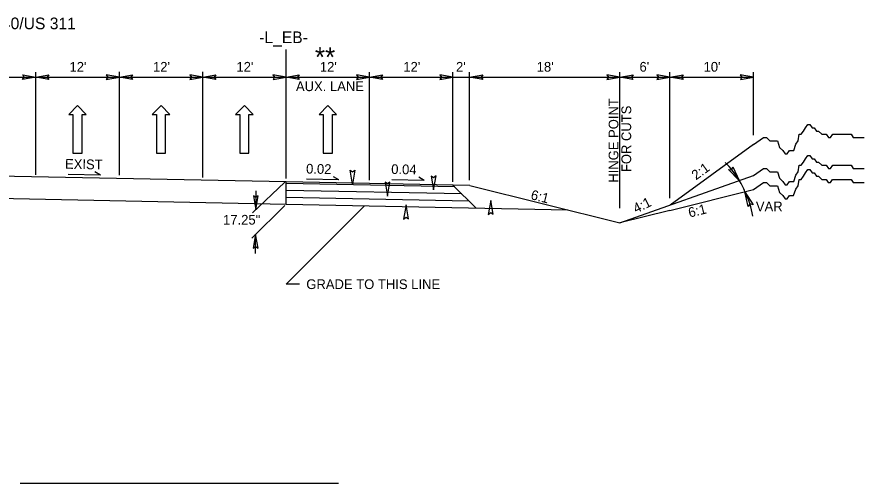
# Model space of a CAD drawing. Extents: x 1725232 to 1728895, y 538685 to 540544.
# Drawn here: x 1727602 to 1728211, y 540208 to 540544 of the extents above; entities that cross this region are included whole.
import ezdxf

# ---------------------------------------------------------------- set-up
doc = ezdxf.new("R2010")
doc.units = 0
for name, color, linetype in [('Default', 7, 'Continuous'), ('Prop Dimension Text', 7, 'Continuous'), ('Typical Hinge Slope Interstate CELL', 7, 'Continuous'), ('Typical Pavement Slope CELL', 7, 'Continuous'), ('Typical Pavement Slope Information CELL', 7, 'Continuous'), ('Typical Terminator CELL', 7, 'Continuous'), ('Typical Text Centerline CELL', 7, 'Continuous'), ('Typical Text General CELL', 7, 'Continuous')]:
    doc.layers.add(name, color=color, linetype=linetype)

msp = doc.modelspace()

# ---------------------------------------------------------------- linework, layer by layer
at = {"layer": 'Default'}
for p, q in [((1727795.33, 540427.18), (1727795.33, 540520.09)), ((1727615.18, 540429.8), (1727615.18, 540503.77)), ((1727675.34, 540429.58), (1727675.34, 540503.92)), ((1727735.39, 540427.79), (1727735.39, 540503.89)), ((1727795.33, 540427.18), (1727795.33, 540503.89)), ((1727855.37, 540425.98), (1727855.37, 540503.77)), ((1727915.42, 540425.98), (1727915.42, 540503.77)), ((1727915.42, 540424.78), (1727915.42, 540503.77)), ((1727927.43, 540425.98), (1727927.43, 540503.77)), ((1728035.55, 540405.77), (1728035.55, 540503.77)), ((1728071.58, 540412.81), (1728071.58, 540503.77)), ((1728131.63, 540458.2), (1728131.63, 540503.77)), ((1727561.09, 540500.07), (1727615.29, 540500.07)), ((1727615.29, 540500.07), (1727675.34, 540500.07)), ((1727675.34, 540500.07), (1727735.39, 540500.07)), ((1727735.39, 540500.07), (1727795.43, 540500.07)), ((1727795.43, 540500.07), (1727855.48, 540500.07)), ((1727855.48, 540500.07), (1727915.53, 540500.07)), ((1727855.48, 540500.07), (1727915.53, 540500.07)), ((1727915.53, 540500.07), (1727927.43, 540500.07)), ((1727927.43, 540500.07), (1728035.51, 540500.07)), ((1728035.51, 540500.07), (1728071.54, 540500.07)), ((1728071.54, 540500.07), (1728131.59, 540500.07)), ((1727645.32, 540479.59), (1727638.92, 540473.29)), ((1727651.52, 540473.29), (1727645.32, 540479.59)), ((1727705.36, 540479.59), (1727698.96, 540473.29)), ((1727711.56, 540473.29), (1727705.36, 540479.59)), ((1727765.41, 540479.59), (1727759.01, 540473.29)), ((1727771.61, 540473.29), (1727765.41, 540479.59)), ((1727825.46, 540479.59), (1727819.06, 540473.29)), ((1727831.66, 540473.29), (1727825.46, 540479.59)), ((1727638.92, 540473.29), (1727641.92, 540473.29)), ((1727641.92, 540473.29), (1727641.92, 540445.29)), ((1727648.52, 540445.29), (1727648.52, 540473.29)), ((1727648.52, 540473.29), (1727651.52, 540473.29)), ((1727698.96, 540473.29), (1727701.96, 540473.29)), ((1727701.96, 540473.29), (1727701.96, 540445.29)), ((1727708.56, 540445.29), (1727708.56, 540473.29)), ((1727708.56, 540473.29), (1727711.56, 540473.29)), ((1727759.01, 540473.29), (1727762.01, 540473.29)), ((1727762.01, 540473.29), (1727762.01, 540445.29)), ((1727768.61, 540445.29), (1727768.61, 540473.29)), ((1727768.61, 540473.29), (1727771.61, 540473.29)), ((1727819.06, 540473.29), (1727822.06, 540473.29)), ((1727822.06, 540473.29), (1727822.06, 540445.29)), ((1727828.66, 540445.29), (1727828.66, 540473.29)), ((1727828.66, 540473.29), (1727831.66, 540473.29)), ((1727641.92, 540445.29), (1727648.52, 540445.29)), ((1727701.96, 540445.29), (1727708.56, 540445.29)), ((1727762.01, 540445.29), (1727768.61, 540445.29)), ((1727822.06, 540445.29), (1727828.66, 540445.29)), ((1727794.5, 540424.56), (1727771.21, 540402.26)), ((1727773.55, 540418.26), (1727773.55, 540404.5)), ((1727794.5, 540407.67), (1727770.67, 540384.19)), ((1727773.43, 540373.15), (1727773.43, 540386.91)), ((1727603.93, 540207.63), (1727833.1, 540207.63))]:
    msp.add_line(p, q, dxfattribs=at)
for points in [[(1727605.81, 540501.69), (1727615.18, 540500.07), (1727605.75, 540498.4), (1727606.95, 540500.07)], [(1727624.56, 540498.45), (1727615.18, 540500.07), (1727624.61, 540501.74), (1727623.42, 540500.07)], [(1727665.96, 540498.45), (1727675.34, 540500.07), (1727665.91, 540501.74), (1727667.11, 540500.07)], [(1727684.72, 540498.45), (1727675.34, 540500.07), (1727684.77, 540501.74), (1727683.57, 540500.07)], [(1727726.01, 540498.45), (1727735.39, 540500.07), (1727725.96, 540501.74), (1727727.16, 540500.07)], [(1727744.77, 540498.45), (1727735.39, 540500.07), (1727744.82, 540501.74), (1727743.62, 540500.07)], [(1727785.95, 540498.45), (1727795.33, 540500.07), (1727785.9, 540501.74), (1727787.09, 540500.07)], [(1727804.7, 540498.45), (1727795.33, 540500.07), (1727804.76, 540501.74), (1727803.56, 540500.07)], [(1727845.99, 540498.45), (1727855.37, 540500.07), (1727845.94, 540501.74), (1727847.14, 540500.07)], [(1727864.75, 540498.45), (1727855.37, 540500.07), (1727864.8, 540501.74), (1727863.6, 540500.07)], [(1727906.04, 540498.45), (1727915.42, 540500.07), (1727905.99, 540501.74), (1727907.19, 540500.07)], [(1727936.81, 540498.45), (1727927.43, 540500.07), (1727936.86, 540501.74), (1727935.66, 540500.07)], [(1728026.17, 540498.46), (1728035.55, 540500.08), (1728026.12, 540501.74), (1728027.32, 540500.08)], [(1728044.93, 540498.46), (1728035.55, 540500.08), (1728044.98, 540501.74), (1728043.78, 540500.08)], [(1728062.2, 540498.46), (1728071.58, 540500.08), (1728062.15, 540501.74), (1728063.35, 540500.08)], [(1728080.96, 540498.46), (1728071.58, 540500.08), (1728081.01, 540501.74), (1728079.81, 540500.08)], [(1728122.21, 540498.45), (1728131.59, 540500.07), (1728122.16, 540501.74), (1728123.36, 540500.07)], [(1728116.91, 540435.57), (1728121.46, 540425.59), (1728113.75, 540433.49), (1728116.12, 540433.43)], [(1728127.83, 540406.84), (1728125.5, 540417.56), (1728131.36, 540408.2), (1728129.06, 540408.76)], [(1728127.83, 540406.84), (1728125.5, 540417.56), (1728131.36, 540408.2), (1728129.06, 540408.76)]]:
    msp.add_lwpolyline(points, close=True, dxfattribs=at)
at = {"layer": 'Typical Hinge Slope Interstate CELL'}
for points in [[(1728131.59, 540451.51), (1728138.81, 540456.57), (1728141.15, 540456.57), (1728143.48, 540454.24), (1728145.04, 540454.24), (1728147.38, 540454.24), (1728148.93, 540454.24), (1728150.49, 540449.55), (1728152.83, 540447.23), (1728154.39, 540444.88), (1728155.94, 540444.88), (1728157.5, 540447.23), (1728159.06, 540447.23), (1728160.61, 540447.23), (1728162.17, 540451.9), (1728163.73, 540454.24), (1728164.51, 540458.92), (1728166.07, 540458.92), (1728167.63, 540461.24), (1728169.18, 540463.59), (1728170.74, 540465.93), (1728172.3, 540465.93), (1728173.85, 540463.59), (1728175.41, 540463.59), (1728176.97, 540461.24), (1728178.53, 540461.24), (1728180.87, 540458.92), (1728182.42, 540458.92), (1728183.98, 540458.92), (1728185.54, 540456.57), (1728187.09, 540456.57), (1728188.65, 540458.92), (1728190.21, 540458.92), (1728191.77, 540458.92), (1728193.32, 540458.92), (1728194.88, 540458.92), (1728197.22, 540458.92), (1728199.55, 540458.92), (1728201.89, 540458.92), (1728203.45, 540456.57), (1728205.78, 540456.57), (1728208.12, 540456.57), (1728211.23, 540456.57)], [(1728131.59, 540429.19), (1728138.81, 540434.26), (1728141.15, 540434.26), (1728143.48, 540431.93), (1728145.04, 540431.93), (1728147.38, 540431.93), (1728148.93, 540431.93), (1728150.49, 540427.24), (1728152.83, 540424.92), (1728154.39, 540422.57), (1728155.94, 540422.57), (1728157.5, 540424.92), (1728159.06, 540424.92), (1728160.61, 540424.92), (1728162.17, 540429.59), (1728163.73, 540431.93), (1728164.51, 540436.6), (1728166.07, 540436.6), (1728167.63, 540438.93), (1728169.18, 540441.28), (1728170.74, 540443.62), (1728172.3, 540443.62), (1728173.85, 540441.28), (1728175.41, 540441.28), (1728176.97, 540438.93), (1728178.53, 540438.93), (1728180.87, 540436.6), (1728182.42, 540436.6), (1728183.98, 540436.6), (1728185.54, 540434.26), (1728187.09, 540434.26), (1728188.65, 540436.6), (1728190.21, 540436.6), (1728191.77, 540436.6), (1728193.32, 540436.6), (1728194.88, 540436.6), (1728197.22, 540436.6), (1728199.55, 540436.6), (1728201.89, 540436.6), (1728203.45, 540434.26), (1728205.78, 540434.26), (1728208.12, 540434.26), (1728211.23, 540434.26)], [(1728131.56, 540419.07), (1728138.77, 540424.14), (1728141.11, 540424.14), (1728143.45, 540421.81), (1728145, 540421.81), (1728147.34, 540421.81), (1728148.9, 540421.81), (1728150.46, 540417.12), (1728152.8, 540414.79), (1728154.35, 540412.45), (1728155.91, 540412.45), (1728157.47, 540414.79), (1728159.03, 540414.79), (1728160.58, 540414.79), (1728162.14, 540419.46), (1728163.7, 540421.81), (1728164.48, 540426.48), (1728166.04, 540426.48), (1728167.59, 540428.81), (1728169.15, 540431.15), (1728170.71, 540433.5), (1728172.26, 540433.5), (1728173.82, 540431.15), (1728175.38, 540431.15), (1728176.94, 540428.81), (1728178.49, 540428.81), (1728180.83, 540426.48), (1728182.39, 540426.48), (1728183.95, 540426.48), (1728185.5, 540424.14), (1728187.06, 540424.14), (1728188.62, 540426.48), (1728190.18, 540426.48), (1728191.73, 540426.48), (1728193.29, 540426.48), (1728194.85, 540426.48), (1728197.19, 540426.48), (1728199.52, 540426.48), (1728201.86, 540426.48), (1728203.42, 540424.14), (1728205.75, 540424.14), (1728208.09, 540424.14), (1728211.2, 540424.14)]]:
    msp.add_lwpolyline(points, dxfattribs=at)
for centre, start, end in [((1728069.06, 540395.64), 29.75191, 45.50364), ((1728071.52, 540390.56), 8.9538, 26.57006), ((1728071.52, 540390.56), 8.9538, 26.57006)]:
    msp.add_arc(centre, 60.35, start, end, dxfattribs=at)
msp.add_ellipse((1728070.97, 540428.62), major_axis=(54.47, -25.99), ratio=0.5, start_param=0.463735, end_param=0.681536, dxfattribs=at)
at = {"layer": 'Typical Pavement Slope CELL'}
for p, q in [((1728131.59, 540451.51), (1728071.62, 540407.89)), ((1727795.33, 540424.71), (1727561.09, 540429.4)), ((1727795.33, 540408.45), (1727795.33, 540424.71)), ((1727927.44, 540422.07), (1727795.33, 540424.71)), ((1727916.7, 540421.05), (1727795.33, 540423.48)), ((1728035.5, 540395.05), (1728131.59, 540429.19)), ((1727921.83, 540415.93), (1727795.33, 540418.46)), ((1727915.42, 540422.33), (1727932.01, 540405.74)), ((1727927.44, 540422.07), (1728035.51, 540395.05)), ((1728071.52, 540404.06), (1728131.56, 540419.07)), ((1727795.33, 540408.45), (1727561.09, 540413.13)), ((1727926.93, 540410.82), (1727795.33, 540413.45)), ((1727998.15, 540404.39), (1727795.33, 540408.45)), ((1728071.52, 540404.06), (1728035.5, 540395.05))]:
    msp.add_line(p, q, dxfattribs=at)
at = {"layer": 'Typical Pavement Slope Information CELL'}
for p, q in [((1727661.73, 540429.46), (1727638.41, 540429.93)), ((1727661.73, 540429.46), (1727657.81, 540431.83)), ((1727833.3, 540426.03), (1727809.99, 540426.5)), ((1727833.3, 540426.03), (1727829.38, 540428.4)), ((1727894.75, 540425.72), (1727871.44, 540426.19)), ((1727894.75, 540425.72), (1727890.84, 540428.09))]:
    msp.add_line(p, q, dxfattribs=at)
at = {"layer": 'Typical Terminator CELL'}
for p, q in [((1727795.32, 540350.93), (1727851.78, 540407.32)), ((1727804.88, 540350.93), (1727795.32, 540350.93))]:
    msp.add_line(p, q, dxfattribs=at)
for points in [[(1727844.91, 540433.1), (1727843.18, 540423.05), (1727841.39, 540433.15), (1727843.18, 540431.87)], [(1727866.52, 540424.5), (1727868.25, 540414.46), (1727870.03, 540424.56), (1727868.25, 540423.28)], [(1727899.78, 540428.89), (1727901.51, 540418.85), (1727903.29, 540428.95), (1727901.51, 540427.66)], [(1727771.82, 540414.55), (1727773.55, 540404.5), (1727775.33, 540414.61), (1727773.55, 540413.32)], [(1727944.38, 540401.3), (1727942.65, 540411.34), (1727940.86, 540401.24), (1727942.65, 540402.52)], [(1727883.38, 540397.96), (1727881.65, 540408.01), (1727879.86, 540397.91), (1727881.65, 540399.19)], [(1727775.16, 540376.86), (1727773.43, 540386.91), (1727771.64, 540376.81), (1727773.43, 540378.09)]]:
    msp.add_lwpolyline(points, close=True, dxfattribs=at)

# ---------------------------------------------------------------- texts
at = {"layer": 'Default'}
msp.add_text('17.25"', height=7.005, rotation=360, dxfattribs=at).set_placement((1727749.98, 540393.86))
at = {"layer": 'Prop Dimension Text'}
for s, p in [("18'", (1727975.66, 540504.07)), ("6'", (1728049.65, 540504.07)), ("10'", (1728095.75, 540504.07)), ('VAR', (1728133.39, 540403.45))]:
    msp.add_text(s, height=7.005, dxfattribs=at).set_placement(p)
for s, height, rotation, p in [('HINGE POINT', 7.0055, 90, (1728034.46, 540424.05)), ('FOR CUTS', 7.005, 90, (1728043.65, 540431.72)), ('2:1', 7.005, 36.02984, (1728090.3, 540425.68)), ('6:1', 7.005, 345.96376, (1727970.91, 540412.26)), ('4:1', 7.005, 26.57006, (1728047.22, 540401.84)), ('6:1', 7.005, 14.03809, (1728085.73, 540398.9))]:
    msp.add_text(s, height=height, rotation=rotation, dxfattribs=at).set_placement(p)
at = {"layer": 'Typical Pavement Slope Information CELL'}
for s, height, p in [('**', 14.011, (1727816.07, 540507.58)), ("12'", 7.005, (1727639.5, 540504.07)), ("12'", 7.005, (1727699.55, 540504.07)), ("12'", 7.005, (1727759.6, 540504.07)), ("12'", 7.005, (1727819.65, 540504.07)), ("12'", 7.005, (1727879.69, 540504.07)), ("2'", 7.005, (1727917.6, 540504.07)), ('AUX. LANE', 7.005, (1727802.43, 540490.06))]:
    msp.add_text(s, height=height, dxfattribs=at).set_placement(p)
for s, p in [('EXIST', (1727636.19, 540434.15)), ('0.02', (1727809.67, 540430.68)), ('0.04', (1727870.93, 540430.38))]:
    msp.add_text(s, height=7.005, rotation=358.85426, dxfattribs=at).set_placement(p)
at = {"layer": 'Typical Text Centerline CELL'}
msp.add_text('-L- I-40/US 311', height=8.4214, rotation=359.94168, dxfattribs=at).set_placement((1727567.06, 540534.69))
msp.add_text('-L_EB-', height=8.421, dxfattribs=at).set_placement((1727775.96, 540524.63))
at = {"layer": 'Typical Text General CELL'}
msp.add_text('GRADE TO THIS LINE', height=7.0055, rotation=360, dxfattribs=at).set_placement((1727809.88, 540347.43))

doc.saveas('drawing.dxf')
